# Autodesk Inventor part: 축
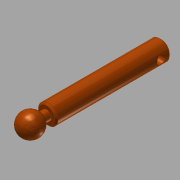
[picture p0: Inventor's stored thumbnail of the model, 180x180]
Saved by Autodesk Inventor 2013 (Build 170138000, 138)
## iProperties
Created: 2017-10
Part Number: 축
Material: 강철, 연강
Document SubType Name: Modeling
Designer: mduedu
Density: 1 g/cm^3
Author: mduedu
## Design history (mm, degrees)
sketch "스케치1"
  geometry: C1 r 6 at (0, 0); 1 further point
  constraints: 1 centre point, 1 coincident
  dimensions: "d0" = 12 diameter of C1
extrude "돌출1" new body sketch "스케치1" distance "d1" = 70; taper "d2" = 0 deg
sketch "스케치2"
  geometry: L1 (7, 80)-(-7, 80); L2 (6, 70)-(-6, 70) reference; A1 r 7 centre (0, 80) between (7, 80) and (-7, 80); 2 further points
  constraints: 2 end point, 2 midpoint, 2 point on circle, 1 centre point, 1 horizontal, 1 vertical alignment
  dimensions: "d3" = 14 diameter of A1; "d5" = 10 distance from line of L2 A1.centre
revolve "회전1" sketch "스케치2" stored, may be unused: angle "d4" = 90 deg
sketch "스케치3"
  geometry: C1 r 3 at (0, 0); 1 further point
  constraints: 1 centre point, 1 coincident
  dimensions: "d6" = 6 diameter of C1
extrude "돌출2" join sketch "스케치3" stored distance "d7" = 70; taper "d8" = 0 deg
chamfer "모따기1" distance "d9" = 1; stored, may be unused: second distance "d10" = 2, angle "d11" = 45 deg
sketch "스케치4"
  geometry: C1 r 2.5 at (0, 6); 1 further point
  constraints: 1 centre point, 1 vertical alignment
  dimensions: "d12" = 5 diameter of C1; "d13" = 6 distance of point (0, 0) C1.centre
extrude "돌출3" cut sketch "스케치4" stored distance "d14" = 70; taper "d15" = 0 deg
sketch "스케치6"
  geometry: A1 r 7 centre (0, 80) between (3, 73.675) and (-3, 73.675) reference; 2 further points
  constraints: 1 coincident
node "작업점1"
node "솔리드1"
